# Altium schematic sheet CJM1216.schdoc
size 127 x 101 mm
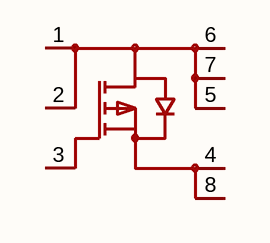
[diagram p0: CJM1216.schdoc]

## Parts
Q?  cjm1216  [DFN-6L_L2.0-W2.0-P0.65-BL_CJM1216]  (value not drawn)

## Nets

Not connected (* = marked no-connect by the designer): Q? 1(D) 2(D) 3(G) 4(S) 5(D) 6(D) 7(D) 8(S)

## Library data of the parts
Q? = cjm1216: 数量:1个P沟道;漏源电压(Vdss):12V;连续漏极电流(Id):16A;导通电阻(RDS(on)):13mΩ@4.5V;耗散功率(Pd):2.5W;阈值电压(Vgs(th)):400mV;; Manufacturer: CJ(江苏长电/长晶); AddInBom: yes; ModelId: 0b3e0b58484e47a2a6bad3a789cc7d0f; ModelName: DFN-6L_L2.0-W2.0-H0.8-P0.65-BL_CJM1216; ModelTransform: 79.527,79.527,0,0,0,0,-2.283,0,0; Number: 1个P沟道; Drain to Source Voltage: 12V; Current - Continuous Drain(Id): 16A; Pd - Power Dissipation: 2.5W; Gate Threshold Voltage (Vgs(th)): 400mV; Gate Charge(Qg): 35nC; Input Capacitance(Ciss): 2.7nF; Reverse Transfer Capacitance (Crss@Vds): 590pF; Type: P沟道; Output Capacitance(Coss): 680pF; Vgs: ±8V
